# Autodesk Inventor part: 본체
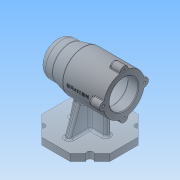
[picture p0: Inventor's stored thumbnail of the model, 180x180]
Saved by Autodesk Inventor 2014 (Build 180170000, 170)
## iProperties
Created: 2021-01
Part Number: 본체
Material: 일반
Document SubType Name: Modeling
Designer: NET
Density: 1 g/cm^3
Appearance: 기본값
Author: NET
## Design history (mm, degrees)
sketch "스케치1"
  geometry: L1 (20.711, 50)-(50, 20.711); L2 (50, 20.711)-(50, -20.711); L3 (50, -20.711)-(20.711, -50); L4 (20.711, -50)-(-20.711, -50); L5 (-20.711, -50)-(-50, -20.711); L6 (-50, -20.711)-(-50, 20.711); L7 (-50, 20.711)-(-20.711, 50); L8 (-20.711, 50)-(20.711, 50); L9 (-35.355, 35.355)-(35.355, -35.355); L10 (35.355, 35.355)-(-35.355, -35.355); L11 (-83.894, 0)-(83.894, 0); C1 r 4.5 at (-35.355, 35.355); C2 r 4.5 at (35.355, 35.355); C3 r 4.5 at (35.355, -35.355); C4 r 4.5 at (-35.355, -35.355); A1 r 50 centre (0, 0) between (0, 50) and (-35.355, -35.355); 3 further points
  constraints: 22 end point, 9 midpoint, 5 centre point, 4 coincident, 4 point on circle, 3 equal radius, 1 parallel, 1 vertical alignment, 17 other
  dimensions: "d0" = 100 diameter of A1; "d1" = 50 distance from line of point (0, 0) L2 (derived); "d2" = 9 diameter of C1; "d3" = 45 deg angle of L11 L9 (derived); "d4" = 45 deg angle of L10 L11 (derived)
extrude "돌출1" new body sketch "스케치1" distance "d5" = 10; taper "d6" = 0 deg
extrude "돌출2" cut sketch "스케치1" distance "d7" = 10; taper "d8" = 0 deg
sketch "스케치2"
  geometry: L1 (-71.975, 75)-(71.964, 75); L2 (-50, 75)-(-50, 105); L3 (-50, 105)-(10, 105); L4 (10, 105)-(30, 100); L5 (30, 100)-(50, 100); L6 (50, 100)-(50, 75); L7 (-50, 75)-(50, 75); 4 further points
  constraints: 14 end point, 3 perpendicular, 2 parallel, 2 vertical alignment, 1 horizontal, 1 midpoint, 1 point on line
  dimensions: "d9" = 75 distance from line of point (0, 0) L1; "d10" = 20 distance from line of L4.end L6; "d11" = 40 distance from line of L6 L3.end; "d12" = 100 distance between parallel lines of L2 L6 (derived); "d13" = 30 distance between parallel lines of L1 L3; "d14" = 25 distance between parallel lines of L1 L5
revolve "회전1" sketch "스케치2" stored, may be unused: angle "d15" = 90 deg
sketch "스케치3"
  geometry: C1 r 30 at (0, 0) reference; C2 r 21 at (0, 0); 1 further point
  constraints: 1 centre point, 1 coincident
  dimensions: "d16" = 42 diameter of C2
extrude "돌출3" cut sketch "스케치3" distance "d17" = 15; taper "d18" = 0 deg
sketch "스케치4"
  geometry: C1 r 21 at (0, 0) reference; C2 r 24 at (0, 0); 1 further point
  constraints: 1 centre point, 1 coincident
  dimensions: "d19" = 48 diameter of C2
extrude "돌출4" cut sketch "스케치4" distance "d20" = 42; taper "d21" = 0 deg
sketch "스케치5"
  geometry: C1 r 24 at (0, 0) reference; C2 r 21 at (0, 0); 1 further point
  constraints: 1 centre point, 1 coincident
  dimensions: "d22" = 42 diameter of C2
extrude "돌출5" cut sketch "스케치5" distance "d23" = 12; taper "d24" = 0 deg
sketch "스케치6"
  geometry: C1 r 21 at (0, 0) reference; C2 r 17.5 at (0, 0); 1 further point
  constraints: 1 centre point, 1 coincident
  dimensions: "d25" = 35 diameter of C2
extrude "돌출6" cut sketch "스케치6" distance "d26" = 18; taper "d27" = 0 deg
sketch "스케치7"
  geometry: C1 r 17.5 at (0, 0) reference; C2 r 16 at (0, 0); 1 further point
  constraints: 1 centre point, 1 coincident
  dimensions: "d28" = 32 diameter of C2
extrude "돌출7" cut sketch "스케치7" distance "d29" = 4; taper "d30" = 0 deg
sketch "스케치8"
  geometry: C1 r 16 at (0, 0) reference; C2 r 10.5 at (0, 0); 1 further point
  constraints: 1 centre point, 1 coincident
  dimensions: "d31" = 21 diameter of C2
extrude "돌출8" cut sketch "스케치8" distance "d32" = 3; taper "d33" = 0 deg
fillet "모깎기1" dims "d34" = 0.3
fillet "모깎기2" dims "d35" = 3
sketch "스케치9"
  geometry: C1 r 21 at (0, 0) reference; C2 r 6 at (-30, 0); C3 r 6 at (0, 30); C4 r 6 at (30, 0); C5 r 6 at (0, -30); A1 r 30 centre (0, 0) between (-30, 0) and (0, 30) reference; 1 further point
  constraints: 4 centre point, 4 point on circle, 3 equal radius, 2 horizontal alignment, 2 vertical alignment
  dimensions: "d37" = 6 radius of C3
extrude "돌출9" join sketch "스케치9" distance "d38" = 16; taper "d39" = 0 deg
sketch "스케치10"
  geometry: A1 r 6 centre (0, 0) between (-0.6, -5.97) and (-0.6, 5.97) reference; A2 r 6 centre (-30, 30) between (-24.03, 29.4) and (-35.97, 29.4) reference; A3 r 6 centre (-60, 0) between (-59.4, 5.97) and (-59.4, -5.97) reference; A4 r 6 centre (-30, -30) between (-35.97, -29.4) and (-24.03, -29.4) reference; 5 further points
  constraints: 4 coincident
hole "구멍1" sketch "스케치10" at (-30, 30), (-60, 0), (0, 0), (-30, -30) diameter "d40" = 3.242; stored, may be unused: countersink angle "d44" = 90 deg, drill point angle "d46" = 118 deg; dims "d41" = 8, "d42" = 4, "d43" = 2, "d45" = 10
fillet "모깎기3" dims "d47" = 3
fillet "모깎기4" dims "d48" = 10
chamfer "모따기1" distance "d49" = 1; stored, may be unused: second distance "d50" = 2, angle "d51" = 45 deg
sketch "스케치11"
  geometry: L1 (50, -20.711)-(50, 20.711) reference; L2 (27, 4)-(0, 4); L3 (0, 4)-(0, -4); L4 (0, -4)-(27, -4); L5 (27, -4)-(27, 4); 2 further points
  constraints: 8 end point, 2 parallel, 1 coincident, 1 horizontal, 1 midpoint, 1 perpendicular
  dimensions: "d52" = 8 distance between parallel lines of L4 L2; "d53" = 23 distance between parallel lines of L1 L5
extrude "돌출10" join sketch "스케치11" stored distance "d54" = 16; taper "d55" = 0 deg
sketch "스케치12"
  geometry: L1 (50, 0)-(-50, 0) reference; L2 (-50, 0)-(-50, 10) reference; L3 (-50, 10)-(-27, 10) reference; L4 (-27, 10)-(-27, 45) reference; L5 (-27, 45)-(-34, 45) reference; L6 (-34, 45)-(-34, 39) reference; L7 (-34, 39)-(-50, 39) reference; L8 (-50, 39)-(-50, 43.379) reference; L9 (-50, 43.379)-(-40, 43.379) reference; L10 (-40, 43.379)-(-39.026, 45) reference; L11 (-39.026, 45)-(-40, 46.621) reference; L12 (-40, 46.621)-(-50, 46.621) reference; L13 (-50, 46.621)-(-50, 53) reference; L14 (-50, 53)-(-49, 54) reference; L15 (-49, 54)-(-35, 54) reference; L16 (-32, 51)-(4, 51) reference; L17 (7, 54)-(18.7, 54) reference; L18 (19, 54.3)-(19, 57.5) reference; L19 (19, 57.5)-(36.7, 57.5) reference; L20 (37, 57.8)-(37, 59) reference; L21 (37, 59)-(40.7, 59) reference; L22 (41, 59.3)-(41, 64.5) reference; L23 (44, 67.5)-(44, 82.5) reference; L24 (41, 85.5)-(41, 90.7) reference; L25 (40.7, 91)-(37, 91) reference; L26 (37, 91)-(37, 92.2) reference; L27 (36.7, 92.5)-(19, 92.5) reference; L28 (19, 92.5)-(19, 95.7) reference; L29 (18.7, 96)-(7, 96) reference; L30 (4, 99)-(-32, 99) reference; L31 (-35, 96)-(-49, 96) reference; L32 (-49, 96)-(-50, 97) reference; L33 (-50, 97)-(-50, 103.379) reference; L34 (-50, 103.379)-(-40, 103.379) reference; L35 (-40, 103.379)-(-39.026, 105) reference; L36 (-39.026, 105)-(-40, 106.621) reference; L37 (-40, 106.621)-(-50, 106.621) reference; L38 (-50, 106.621)-(-50, 111) reference; L39 (-50, 111)-(-34, 111) reference; L40 (-34, 111)-(-34, 105) reference; L41 (-34, 105)-(9.631, 105) reference; L42 (10.358, 104.91)-(29.642, 100.09) reference; L43 (30.369, 100)-(40, 100) reference; L44 (50, 90)-(50, 60) reference; L45 (40, 50)-(30.369, 50) reference; L46 (29.642, 49.91)-(10.358, 45.09) reference; L47 (9.631, 45)-(0, 45) reference; L48 (0, 45)-(0, 10) reference; L49 (0, 10)-(50, 10) reference; L50 (50, 10)-(50, 0) reference; L51 (27, 10)-(19.724, 47.431); A1 r 3 centre (-32, 54) between (-35, 54) and (-32, 51) reference; A2 r 3 centre (4, 54) between (4, 51) and (7, 54) reference; A3 r 0.3 centre (18.7, 54.3) between (18.7, 54) and (19, 54.3) reference; A4 r 0.3 centre (36.7, 57.8) between (36.7, 57.5) and (37, 57.8) reference; A5 r 0.3 centre (40.7, 59.3) between (40.7, 59) and (41, 59.3) reference; A6 r 3 centre (41, 67.5) between (41, 64.5) and (44, 67.5) reference; A7 r 3 centre (41, 82.5) between (44, 82.5) and (41, 85.5) reference; A8 r 0.3 centre (40.7, 90.7) between (41, 90.7) and (40.7, 91) reference; A9 r 0.3 centre (36.7, 92.2) between (37, 92.2) and (36.7, 92.5) reference; A10 r 0.3 centre (18.7, 95.7) between (19, 95.7) and (18.7, 96) reference; A11 r 3 centre (4, 96) between (7, 96) and (4, 99) reference; A12 r 3 centre (-32, 96) between (-32, 99) and (-35, 96) reference; A13 r 3 centre (9.631, 102) between (10.358, 104.91) and (9.631, 105) reference; A14 r 3 centre (30.369, 103) between (29.642, 100.09) and (30.369, 100) reference; A15 r 10 centre (40, 90) between (50, 90) and (40, 100) reference; A16 r 10 centre (40, 60) between (40, 50) and (50, 60) reference; A17 r 3 centre (30.369, 47) between (30.369, 50) and (29.642, 49.91) reference; A18 r 3 centre (9.631, 48) between (9.631, 45) and (10.358, 45.09) reference; 1 further point
  constraints: 2 end point, 2 point on line
  dimensions: "d56" = 23 distance from line of L50 L51.start; "d57" = 101 deg angle of L49 L51
feature "리브1" sketch "스케치12" dims "d58" = 1, "d59" = 8, "d60" = 0, "d61" = 0, "d62" = 1, "d63" = 1
sketch "스케치13"
  geometry: L1 (-50, 10)-(-4, 10) reference; L2 (-4, 10)-(-4, 45.268) reference; L3 (4, 45.268)-(4, 10) reference; L4 (4, 10)-(50, 10) reference; L5 (50, 10)-(50, 0) reference; L6 (50, 0)-(-50, 0) reference; L7 (-50, 0)-(-50, 10) reference; L8 (-19.606, 52.293)-(-35, 10); L9 (19.606, 52.293)-(35, 10); C1 r 24 at (0, 75) reference; A1 r 30 centre (0, 75) between (4, 45.268) and (-4, 45.268) reference; 1 further point
  constraints: 4 end point, 2 point on circle, 2 point on line
  dimensions: "d64" = 15 distance from line of L7 L8.end; "d65" = 15 distance from line of L5 L9.end; "d66" = 110 deg angle of L4 L9; "d67" = 110 deg angle of L1 L8
  node "절단 모서리 투영2"
feature "리브2" dims "d68" = 1, "d69" = 8, "d70" = 0, "d71" = 0, "d72" = 1, "d73" = 1
feature "리브3" dims "d74" = 1, "d75" = 8, "d76" = 0, "d77" = 0, "d78" = 1, "d79" = 1
fillet "모깎기5" dims "d80" = 3
fillet "모깎기6" dims "d81" = 1
node "작업 평면1"
sketch "스케치14"
  geometry: L1 (30, 36)-(30, 30.171) reference; L2 (-70, -15)-(-70, 15) reference; L3 (-70, 0)-(32.232, 0); 2 further points
  constraints: 2 end point, 1 midpoint, 1 perpendicular, 1 point on line, 1 other
  dimensions: "d82" = 38 horizontal distance of L1.start point (-8, 0)
feature "엠보싱1" sketch "스케치14" dims "d83" = 0.5, "d84" = 0
fillet "모깎기7" dims "d85" = 3
fillet "모깎기8" dims "d86" = 3
node "솔리드1"
node "절단 모서리 투영1"
